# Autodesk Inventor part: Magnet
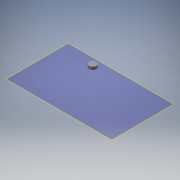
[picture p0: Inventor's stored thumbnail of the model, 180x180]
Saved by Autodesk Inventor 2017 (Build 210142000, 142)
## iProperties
Created: 2017-05
Part Number: Magnet
Material: Generic
Document SubType Name: Modeling
Designer: Savy
Density: 1 g/cm^3
Appearance: Default
Author: Savy
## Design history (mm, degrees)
workplane "Work Plane1"
sketch "Sketch1"
  geometry: C1 r 4 at (-22.225, 25.4) reference; C2 r 4 at (-22.225, 25.4); 1 further point
  constraints: 1 centre point, 1 coincident, 1 concentric
extrude "Extrusion1" new body sketch "Sketch1" distance "d0" = 3.175; taper "d1" = 0 deg
body "Solid1"
node "Reference1"
